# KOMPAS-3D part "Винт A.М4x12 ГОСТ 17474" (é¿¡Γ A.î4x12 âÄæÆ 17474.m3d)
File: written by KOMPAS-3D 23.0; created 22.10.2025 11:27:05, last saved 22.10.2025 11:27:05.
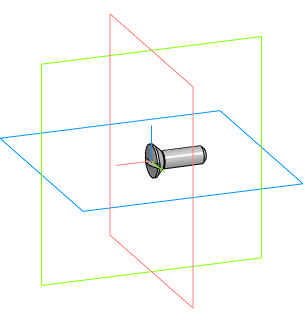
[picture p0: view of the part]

Document properties: Автор: ARM_513_VVK; Полное имя файла: F:\Демо\Демо вариант авиация\Винт A.М4x12 ГОСТ 17474.m3d

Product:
- Part/product: Винт A.М4x12 ГОСТ 17474

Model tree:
1. Операция без истории:1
